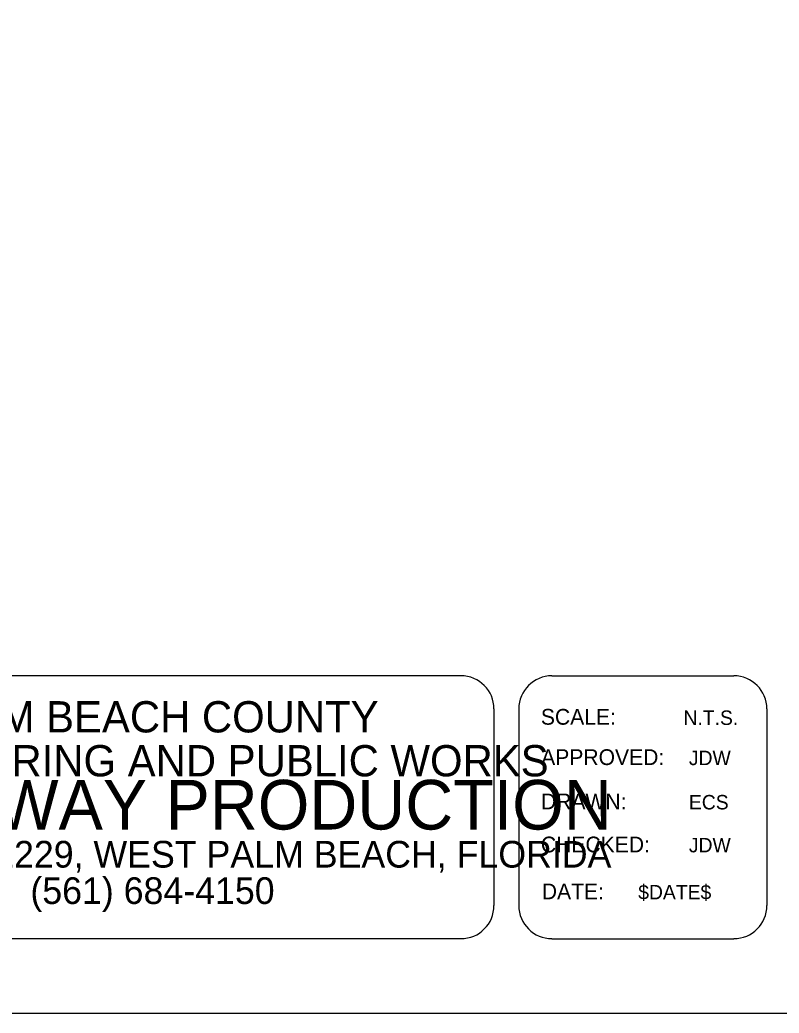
# Model space of a CAD drawing. Extents: x -0.7 to 16, y -0.9 to 9.7.
# Drawn here: x 9.999 to 12.024, y -0.9 to 1.75 of the extents above; entities that cross this region are included whole.
import ezdxf

# ---------------------------------------------------------------- set-up
doc = ezdxf.new("R2010")
doc.units = 0
doc.layers.add('Default', color=7, linetype='Continuous')
doc.layers.add('PlotBorder_dp', color=7, linetype='Continuous')

msp = doc.modelspace()

# ---------------------------------------------------------------- linework, layer by layer
at = {"layer": 'Default'}
for p, q in [((11.1756, 0), (8.7497, 0)), ((11.4182, 0), (11.9034, 0)), ((11.2638, -0.0882), (11.2638, -0.6131)), ((11.33, -0.0882), (11.33, -0.6131)), ((11.9916, -0.0882), (11.9916, -0.6131)), ((11.1756, -0.7014), (8.7497, -0.7014)), ((11.4182, -0.7014), (11.9034, -0.7014))]:
    msp.add_line(p, q, dxfattribs=at)
for centre, major_axis, start_param, end_param in [((11.1756, -0.0882), (0, 0.0882), 4.712389, 6.283185), ((11.4182, -0.0882), (0, 0.0882), 0, 1.570796), ((11.9034, -0.0882), (0, 0.0882), 4.712389, 6.283185), ((11.1756, -0.6131), (0, 0.0882), 3.141593, 4.712389), ((11.4182, -0.6131), (0, -0.0882), 4.712389, 6.283185), ((11.9034, -0.6131), (0, -0.0882), 0, 1.570796)]:
    msp.add_ellipse(centre, major_axis=major_axis, ratio=0.999927, start_param=start_param, end_param=end_param, dxfattribs=at)
at = {"layer": 'PlotBorder_dp'}
msp.add_lwpolyline([(-0.55, -0.9), (15.95, -0.9), (15.95, 9.7), (-0.55, 9.7)], close=True, dxfattribs=at)

# ---------------------------------------------------------------- texts
at = {"layer": 'Default'}
for s, height, p in [('PALM BEACH COUNTY', 0.083446, (9.7345, -0.1511)), ('ENGINEERING AND PUBLIC WORKS', 0.083468, (9.4745, -0.2683)), ('ROADWAY PRODUCTION', 0.132369, (9.4241, -0.4101)), ('P.O. BOX 21229, WEST PALM BEACH, FLORIDA', 0.071224, (9.4333, -0.5117)), ('(561) 684-4150', 0.071224, (10.0274, -0.6088))]:
    msp.add_text(s, height=height, rotation=360, dxfattribs=at).set_placement(p)
for s, height, p in [('SCALE:', 0.04207, (11.3888, -0.1305)), ('N.T.S.', 0.03855, (11.7691, -0.1311)), ('APPROVED:', 0.04207, (11.3896, -0.2381)), ('JDW', 0.03855, (11.7836, -0.2384)), ('DRAWN:', 0.04207, (11.389, -0.3563)), ('ECS', 0.03855, (11.7836, -0.3565)), ('CHECKED:', 0.04207, (11.3889, -0.4711)), ('JDW', 0.03855, (11.7836, -0.471)), ('DATE:', 0.04207, (11.3913, -0.5963)), ('$DATE$', 0.03855, (11.6484, -0.5965))]:
    msp.add_text(s, height=height, dxfattribs=at).set_placement(p)

doc.saveas('drawing.dxf')
